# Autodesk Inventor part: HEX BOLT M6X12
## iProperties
Created: 2011-07
Part Number: HEX BOLT M6X12
Document SubType Name: Modeling
Designer: Administrator
Density: 7.85 g/cm^3
Material: Steel
Mass: 4.85689 g
Surface Area: 6.07211 cm^2
Volume: 0.618712 cm^3
Author: Administrator
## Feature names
1. Base1
